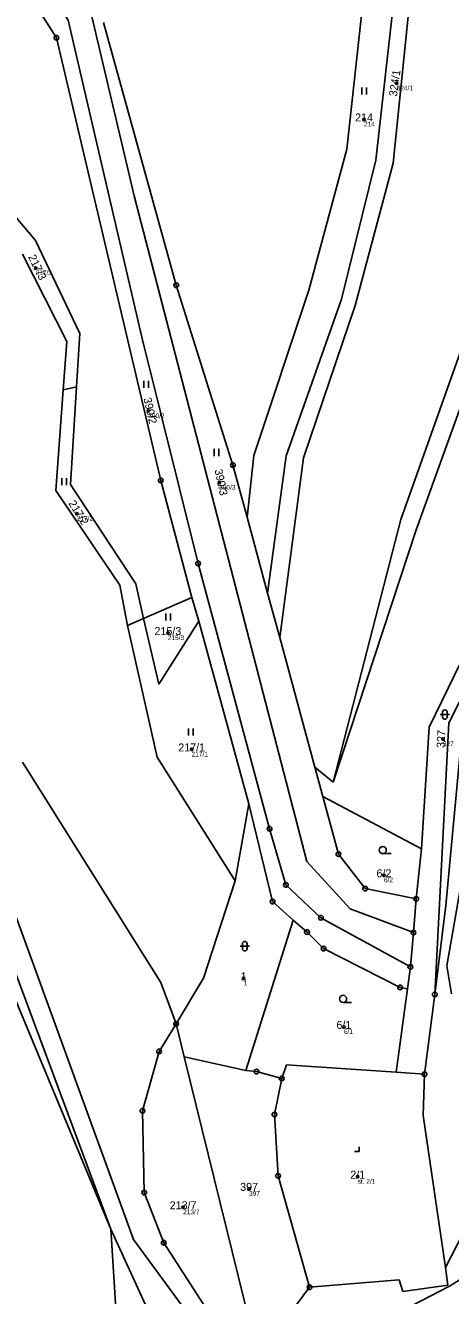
# Model space of a CAD drawing. Extents: x -867966 to -864255, y -1043242 to -1041327.
# Drawn here: x -865182 to -865091.7, y -1042444.5 to -1042174.8 of the extents above; entities that cross this region are included whole.
import ezdxf

# ---------------------------------------------------------------- set-up
doc = ezdxf.new("R2010")
doc.units = 0
for name, color, linetype in [('Definiční body', 7, 'Continuous'), ('Hranice parcel', 7, 'Continuous'), ('Parcelní čísla', 7, 'Continuous'), ('Vnitřní kresba', 7, 'Continuous'), ('Věcná břemena k části', 7, 'Continuous'), ('Značky bodu BP', 7, 'Continuous'), ('Značky kultur', 7, 'Continuous')]:
    doc.layers.add(name, color=color, linetype=linetype)

msp = doc.modelspace()

# ---------------------------------------------------------------- linework, layer by layer
at = {"layer": 'Definiční body'}
for centre in [(-865103.12, -1042187.11), (-865110.06, -1042194.77), (-865179.82, -1042226.32), (-865155.88, -1042256.7), (-865140.81, -1042271.9), (-865171.06, -1042278.47), (-865151.73, -1042303.83), (-865093.29, -1042326.36), (-865146.68, -1042328.56), (-865105.83, -1042355.27), (-865135.63, -1042377.17), (-865114.34, -1042387.47), (-865111.41, -1042419.28), (-865134.47, -1042421.86), (-865148.49, -1042425.77)]:
    msp.add_circle(centre, 0.25, dxfattribs=at)
at = {"layer": 'Hranice parcel'}
for p, q in [((-865108.1, -1042150.06), (-865113.74, -1042201.06)), ((-865101.64, -1042150.61), (-865107.55, -1042203.4)), ((-865098.48, -1042151.16), (-865103.84, -1042204.08)), ((-865175.41, -1042177.41), (-865185.01, -1042162.21)), ((-865158.9, -1042210.99), (-865168.23, -1042171.45)), ((-865172.92, -1042173.7), (-865157.25, -1042241.01)), ((-865165.38, -1042174.15), (-865149.93, -1042229.98)), ((-865153.25, -1042271.42), (-865175.41, -1042177.41)), ((-865102.25, -1042279.75), (-865067.76, -1042182.54)), ((-865063.63, -1042183.64), (-865098.95, -1042281.95)), ((-865113.74, -1042201.06), (-865121.8, -1042231.03)), ((-865179.82, -1042220.47), (-865193.22, -1042204.64)), ((-865107.55, -1042203.4), (-865114.86, -1042232.95)), ((-865103.84, -1042204.08), (-865111.91, -1042234.26)), ((-865122.2, -1042352.37), (-865158.9, -1042210.99)), ((-865170.43, -1042240.25), (-865179.82, -1042220.47)), ((-865182.58, -1042223.38), (-865173.19, -1042241.94)), ((-865149.93, -1042229.98), (-865137.91, -1042268.15)), ((-865121.8, -1042231.03), (-865133.48, -1042266.11)), ((-865114.86, -1042232.95), (-865126.58, -1042266.17)), ((-865111.91, -1042234.26), (-865122.94, -1042266.6)), ((-865171.13, -1042251.52), (-865170.43, -1042240.25)), ((-865173.19, -1042241.94), (-865173.95, -1042252.17)), ((-865157.25, -1042241.01), (-865145.3, -1042289.05)), ((-865173.95, -1042252.17), (-865175.54, -1042273.56)), ((-865173.95, -1042252.17), (-865171.13, -1042251.52)), ((-865172.43, -1042272.31), (-865171.13, -1042251.52)), ((-865133.48, -1042266.11), (-865134.91, -1042279.2)), ((-865126.58, -1042266.17), (-865130.54, -1042295.33)), ((-865122.94, -1042266.6), (-865127.97, -1042304.8)), ((-865137.91, -1042268.15), (-865134.91, -1042279.2)), ((-865172.43, -1042272.31), (-865158.56, -1042293.41)), ((-865146.61, -1042296.29), (-865153.25, -1042271.42)), ((-865161.95, -1042293.67), (-865175.54, -1042273.56)), ((-865134.91, -1042279.2), (-865130.54, -1042295.33)), ((-865116.63, -1042335.5), (-865102.25, -1042279.75)), ((-865098.95, -1042281.95), (-865116.63, -1042335.5)), ((-865145.3, -1042289.05), (-865130.11, -1042345.38)), ((-865160.29, -1042302.23), (-865161.95, -1042293.67)), ((-865158.56, -1042293.41), (-865156.87, -1042300.75)), ((-865080.75, -1042291.96), (-865096.19, -1042323.81)), ((-865077.61, -1042294.34), (-865092.04, -1042322.88)), ((-865146.61, -1042296.29), (-865156.87, -1042300.75)), ((-865145.16, -1042301.34), (-865146.61, -1042296.29)), ((-865130.54, -1042295.33), (-865127.97, -1042304.8)), ((-865156.87, -1042300.75), (-865160.29, -1042302.23)), ((-865160.29, -1042302.23), (-865154, -1042330.22)), ((-865156.87, -1042300.75), (-865153.63, -1042314.72)), ((-865153.63, -1042314.72), (-865145.16, -1042301.34)), ((-865145.16, -1042301.34), (-865134.52, -1042340.07)), ((-865127.97, -1042304.8), (-865120.5, -1042332.33)), ((-865097.82, -1042349.69), (-865096.19, -1042323.81)), ((-865095.02, -1042380.58), (-865092.04, -1042322.88)), ((-865092.71, -1042361.69), (-865089.14, -1042323.85)), ((-865153.24, -1042378.03), (-865182.59, -1042331.27)), ((-865154, -1042330.22), (-865137.42, -1042356.44)), ((-865120.5, -1042332.33), (-865116.63, -1042335.5)), ((-865120.5, -1042332.33), (-865118.8, -1042338.57)), ((-865092.46, -1042374.48), (-865085.38, -1042333.74)), ((-865159.06, -1042432.65), (-865193.03, -1042339.27)), ((-865137.42, -1042356.44), (-865134.52, -1042340.07)), ((-865134.52, -1042340.07), (-865129.48, -1042360.86)), ((-865097.82, -1042349.69), (-865118.8, -1042338.57)), ((-865118.8, -1042338.57), (-865115.49, -1042350.77)), ((-865163.86, -1042430.4), (-865201.06, -1042341.02)), ((-865196.64, -1042342.29), (-865163.86, -1042430.4)), ((-865126.65, -1042357.31), (-865130.11, -1042345.38)), ((-865115.49, -1042350.77), (-865109.83, -1042358.09)), ((-865098.98, -1042360.3), (-865097.82, -1042349.69)), ((-865112.98, -1042362.43), (-865122.2, -1042352.37)), ((-865144.19, -1042377.1), (-865137.42, -1042356.44)), ((-865119.23, -1042364.28), (-865126.65, -1042357.31)), ((-865109.83, -1042358.09), (-865098.98, -1042360.3)), ((-865129.48, -1042360.86), (-865125.09, -1042364.79)), ((-865098.98, -1042360.3), (-865099.56, -1042367.45)), ((-865095.02, -1042380.58), (-865092.71, -1042361.69)), ((-865100.22, -1042374.74), (-865119.23, -1042364.28)), ((-865099.56, -1042367.45), (-865112.98, -1042362.43)), ((-865125.09, -1042364.79), (-865135.16, -1042396.75)), ((-865122.17, -1042367.34), (-865125.09, -1042364.79)), ((-865118.64, -1042370.84), (-865122.17, -1042367.34)), ((-865100.22, -1042374.74), (-865099.56, -1042367.45)), ((-865102.4, -1042379.08), (-865118.64, -1042370.84)), ((-865100.22, -1042374.74), (-865100.85, -1042379.4)), ((-865091.46, -1042380.48), (-865092.46, -1042374.48)), ((-865149.98, -1042386.82), (-865153.24, -1042378.03)), ((-865149.98, -1042386.82), (-865144.19, -1042377.1)), ((-865100.85, -1042379.4), (-865103.24, -1042397.1)), ((-865102.4, -1042379.08), (-865100.85, -1042379.4)), ((-865095.02, -1042380.58), (-865097.21, -1042397.51)), ((-865149.98, -1042386.82), (-865153.58, -1042392.67)), ((-865149.98, -1042386.82), (-865148.26, -1042393.81)), ((-865153.58, -1042392.67), (-865157.12, -1042405.29)), ((-865135.16, -1042396.75), (-865148.26, -1042393.81)), ((-865148.26, -1042393.81), (-865132.06, -1042459.62)), ((-865135.16, -1042396.75), (-865132.88, -1042396.95)), ((-865132.88, -1042396.95), (-865127.55, -1042398.42)), ((-865127.55, -1042398.42), (-865126.53, -1042395.51)), ((-865126.53, -1042395.51), (-865103.24, -1042397.1)), ((-865129.1, -1042406.08), (-865127.55, -1042398.42)), ((-865103.24, -1042397.1), (-865097.21, -1042397.51)), ((-865097.47, -1042406.27), (-865097.21, -1042397.51)), ((-865157.12, -1042405.29), (-865156.74, -1042422.65)), ((-865128.3, -1042419.1), (-865129.1, -1042406.08)), ((-865092.78, -1042438.53), (-865097.47, -1042406.27)), ((-865121.63, -1042442.76), (-865128.3, -1042419.1)), ((-865156.74, -1042422.65), (-865152.61, -1042433.29)), ((-865087.67, -1042428.68), (-865092.78, -1042438.53)), ((-865160.89, -1042476.19), (-865163.86, -1042430.4)), ((-865163.86, -1042430.4), (-865139.14, -1042484.06)), ((-865132.89, -1042468.19), (-865159.06, -1042432.65)), ((-865152.61, -1042433.29), (-865134.61, -1042461.15)), ((-865092.23, -1042442.29), (-865092.78, -1042438.53)), ((-865126.13, -1042448.77), (-865121.63, -1042442.76)), ((-865121.63, -1042442.76), (-865102.61, -1042441.19)), ((-865102.61, -1042441.19), (-865101.84, -1042443.67)), ((-865101.84, -1042443.67), (-865092.23, -1042442.29))]:
    msp.add_line(p, q, dxfattribs=at)
at = {"layer": 'Vnitřní kresba'}
for p, q in [((-865091.87, -1042442.55), (-865065.5, -1042425.92)), ((-865133.07, -1042463.7), (-865091.87, -1042442.55))]:
    msp.add_line(p, q, dxfattribs=at)
at = {"layer": 'Věcná břemena k části'}
msp.add_lwpolyline([(-865175.78, -1042158.38), (-865195.82, -1042138.48), (-865194.06, -1042136.88), (-865197.31, -1042134.96), (-865215.64, -1042112.12), (-865201.15, -1042134.69), (-865204.23, -1042137.72), (-865199.55, -1042141.89), (-865197.64, -1042144.76), (-865181.91, -1042159.32), (-865172.92, -1042173.7), (-865157.25, -1042241.01), (-865145.3, -1042289.05), (-865130.11, -1042345.38), (-865126.65, -1042357.31), (-865119.23, -1042364.28), (-865100.22, -1042374.74), (-865099.56, -1042367.45), (-865112.98, -1042362.43), (-865122.2, -1042352.37), (-865158.9, -1042210.99), (-865168.23, -1042171.45)], close=True, dxfattribs=at)
at = {"layer": 'Značky bodu BP'}
for centre, radius in [((-865175.41, -1042177.41), 0.5), ((-865175.41, -1042177.41), 0.0303), ((-865149.93, -1042229.98), 0.5), ((-865149.93, -1042229.98), 0.0303), ((-865137.91, -1042268.15), 0.5), ((-865137.91, -1042268.15), 0.0303), ((-865153.25, -1042271.42), 0.5), ((-865153.25, -1042271.42), 0.0303), ((-865145.3, -1042289.05), 0.5), ((-865145.3, -1042289.05), 0.0303), ((-865130.11, -1042345.38), 0.5), ((-865130.11, -1042345.38), 0.0303), ((-865115.49, -1042350.77), 0.5), ((-865115.49, -1042350.77), 0.0303), ((-865126.65, -1042357.31), 0.5), ((-865126.65, -1042357.31), 0.0303), ((-865109.83, -1042358.09), 0.5), ((-865109.83, -1042358.09), 0.0303), ((-865129.48, -1042360.86), 0.5), ((-865129.48, -1042360.86), 0.0303), ((-865098.98, -1042360.3), 0.5), ((-865098.98, -1042360.3), 0.0303), ((-865119.23, -1042364.28), 0.5), ((-865119.23, -1042364.28), 0.0303), ((-865122.17, -1042367.34), 0.5), ((-865099.56, -1042367.45), 0.5), ((-865122.17, -1042367.34), 0.0303), ((-865099.56, -1042367.45), 0.0303), ((-865118.64, -1042370.84), 0.5), ((-865118.64, -1042370.84), 0.0303), ((-865100.22, -1042374.74), 0.5), ((-865100.22, -1042374.74), 0.0303), ((-865102.4, -1042379.08), 0.5), ((-865102.4, -1042379.08), 0.0303), ((-865095.02, -1042380.58), 0.5), ((-865095.02, -1042380.58), 0.0303), ((-865149.98, -1042386.82), 0.5), ((-865149.98, -1042386.82), 0.0303), ((-865153.58, -1042392.67), 0.5), ((-865153.58, -1042392.67), 0.0303), ((-865132.88, -1042396.95), 0.5), ((-865132.88, -1042396.95), 0.0303), ((-865127.55, -1042398.42), 0.5), ((-865127.55, -1042398.42), 0.0303), ((-865097.21, -1042397.51), 0.5), ((-865097.21, -1042397.51), 0.0303), ((-865157.12, -1042405.29), 0.5), ((-865157.12, -1042405.29), 0.0303), ((-865129.1, -1042406.08), 0.5), ((-865129.1, -1042406.08), 0.0303), ((-865128.3, -1042419.1), 0.5), ((-865128.3, -1042419.1), 0.0303), ((-865156.74, -1042422.65), 0.5), ((-865156.74, -1042422.65), 0.0303), ((-865152.61, -1042433.29), 0.5), ((-865152.61, -1042433.29), 0.0303), ((-865121.63, -1042442.76), 0.5), ((-865121.63, -1042442.76), 0.0303)]:
    msp.add_circle(centre, radius, dxfattribs=at)
at = {"layer": 'Značky kultur'}
for p, q in [((-865110.5, -1042189.47), (-865110.5, -1042187.97)), ((-865109.5, -1042189.47), (-865109.5, -1042187.97)), ((-865156.82, -1042251.79), (-865156.82, -1042250.29)), ((-865155.82, -1042251.79), (-865155.82, -1042250.29)), ((-865141.87, -1042266.25), (-865141.87, -1042264.75)), ((-865140.87, -1042266.25), (-865140.87, -1042264.75)), ((-865174.25, -1042272.46), (-865174.25, -1042270.96)), ((-865173.25, -1042272.46), (-865173.25, -1042270.96)), ((-865152.18, -1042301.17), (-865152.18, -1042299.67)), ((-865151.18, -1042301.17), (-865151.18, -1042299.67)), ((-865093.88, -1042321.14), (-865091.88, -1042321.14)), ((-865093.38, -1042320.64), (-865093.38, -1042321.64)), ((-865092.38, -1042321.64), (-865092.38, -1042320.64)), ((-865147.37, -1042325.6), (-865147.37, -1042324.1)), ((-865146.37, -1042325.6), (-865146.37, -1042324.1)), ((-865106.08, -1042350.68), (-865104.33, -1042350.68)), ((-865135.88, -1042369.83), (-865135.88, -1042370.83)), ((-865134.88, -1042370.83), (-865134.88, -1042369.83)), ((-865136.38, -1042370.33), (-865134.38, -1042370.33)), ((-865114.5, -1042382.26), (-865112.75, -1042382.26)), ((-865111.07, -1042413.96), (-865111.07, -1042412.96)), ((-865112.07, -1042413.96), (-865111.07, -1042413.96))]:
    msp.add_line(p, q, dxfattribs=at)
for centre in [(-865106.08, -1042349.93), (-865114.5, -1042381.51)]:
    msp.add_circle(centre, 0.75, dxfattribs=at)
for centre, start, end in [((-865092.88, -1042320.64), 0, 180), ((-865092.88, -1042321.64), 180, 359.9879), ((-865135.38, -1042369.83), 0, 180), ((-865135.38, -1042370.83), 180, 359.9879)]:
    msp.add_arc(centre, 0.5, start, end, dxfattribs=at)

# ---------------------------------------------------------------- texts
at = {"layer": 'Definiční body'}
for s, p in [('324/1', (-865103.12, -1042188.6)), ('214', (-865110.06, -1042196.26)), ('217/3', (-865179.82, -1042227.81)), ('390/2', (-865155.88, -1042258.19)), ('390/3', (-865140.81, -1042273.39)), ('217/2', (-865171.06, -1042279.96)), ('215/3', (-865151.73, -1042305.32)), ('327', (-865093.29, -1042327.85)), ('217/1', (-865146.68, -1042330.05)), ('6/2', (-865105.83, -1042356.76)), ('1', (-865135.63, -1042378.66)), ('6/1', (-865114.34, -1042388.96)), ('st. 2/1', (-865111.41, -1042420.77)), ('397', (-865134.47, -1042423.35)), ('213/7', (-865148.49, -1042427.26))]:
    msp.add_text(s, height=1, dxfattribs=at).set_placement(p)
at = {"layer": 'Parcelní čísla'}
for s, rotation, p in [('324/1', 82, (-865103.09, -1042189.98)), ('217/3', 296, (-865181.45, -1042223.96)), ('390/2', 283, (-865156.93, -1042254.03)), ('390/3', 282, (-865141.82, -1042269.21)), ('217/2', 302, (-865172.92, -1042276.29)), ('327', 87, (-865092.96, -1042328.27))]:
    msp.add_text(s, height=1.7, rotation=rotation, dxfattribs=at).set_placement(p)
for s, p in [('214', (-865111.95, -1042195.2)), ('215/3', (-865154.57, -1042304.26)), ('217/1', (-865149.52, -1042328.98)), ('6/2', (-865107.41, -1042355.7)), ('1', (-865136.26, -1042377.59)), ('6/1', (-865115.92, -1042387.9)), ('2/1', (-865112.98, -1042419.71)), ('397', (-865136.36, -1042422.29)), ('213/7', (-865151.33, -1042426.2))]:
    msp.add_text(s, height=1.7, dxfattribs=at).set_placement(p)

doc.saveas('drawing.dxf')
